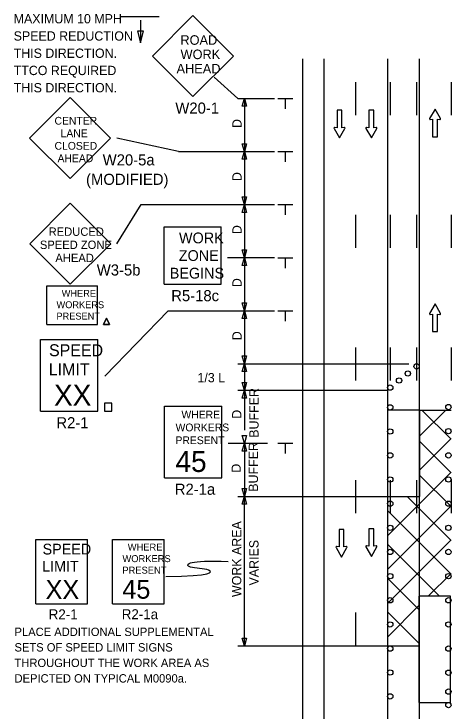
# Model space of a CAD drawing. Extents: x 16730 to 18475, y 5651 to 6927.
# Drawn here: x 16730 to 17059, y 6401 to 6927 of the extents above; entities that cross this region are included whole.
import ezdxf

# ---------------------------------------------------------------- set-up
doc = ezdxf.new("R2010")
doc.units = 0
for name, color, linetype in [('ALI_LEGAL_EX', 7, 'Continuous'), ('Level 6', 7, 'Continuous'), ('MT_SCRATCH_LEVEL_A', 7, 'Continuous'), ('MT_SCRATCH_LEVEL_E', 7, 'Continuous'), ('PAVT_EDGE_EX', 7, 'Continuous'), ('TRAFFIC_SIGNS_PR', 7, 'Continuous'), ('TYPICAL_TEXT_DIMEN_PR', 7, 'Continuous')]:
    doc.layers.add(name, color=color, linetype=linetype)

msp = doc.modelspace()

# ---------------------------------------------------------------- linework, layer by layer
at = {"layer": 'ALI_LEGAL_EX'}
for points in [[(16987.43, 6875.6), (16987.43, 6850.6)], [(17013.43, 6875.6), (17013.43, 6850.6)], [(17033.43, 6875.6), (17033.43, 6850.6)], [(17059.43, 6875.6), (17059.43, 6850.6)], [(16987.43, 6775.6), (16987.43, 6750.6)], [(17013.43, 6775.6), (17013.43, 6750.6)], [(17033.43, 6775.6), (17033.43, 6750.6)], [(17059.43, 6775.6), (17059.43, 6750.6)], [(16987.43, 6675.6), (16987.43, 6650.6)], [(17013.43, 6675.6), (17013.43, 6650.6)], [(17033.43, 6675.6), (17033.43, 6650.6)], [(17059.43, 6675.6), (17059.43, 6650.6)], [(16987.43, 6575.6), (16987.43, 6550.6)], [(17013.43, 6575.6), (17013.43, 6550.6)], [(17033.43, 6575.6), (17033.43, 6550.6)], [(17059.43, 6575.6), (17059.43, 6550.6)], [(16987.43, 6475.6), (16987.43, 6450.6)]]:
    msp.add_lwpolyline(points, dxfattribs=at)
at = {"layer": 'Level 6'}
for p, q in [((16843.25, 6631.37), (16886.45, 6631.37)), ((16843.25, 6577.37), (16843.25, 6631.37)), ((16886.45, 6577.37), (16886.45, 6631.37)), ((16843.25, 6577.37), (16886.45, 6577.37))]:
    msp.add_line(p, q, dxfattribs=at)
at = {"layer": 'MT_SCRATCH_LEVEL_A'}
for p, q in [((17011.43, 6628.39), (17011.43, 6450.54)), ((17035.43, 6628.39), (17059.43, 6628.39)), ((17035.84, 6608.83), (17055.4, 6628.39)), ((17059.43, 6606.43), (17037.48, 6628.39)), ((17035.84, 6583.37), (17059.43, 6606.97)), ((17059.43, 6580.97), (17035.84, 6604.57)), ((17011.43, 6596.33), (17011.43, 6482.6)), ((17011.43, 6533.52), (17059.43, 6581.52)), ((17059.43, 6555.52), (17035.84, 6579.12)), ((17059.43, 6530.06), (17026.21, 6563.29)), ((17011.43, 6508.06), (17059.43, 6556.06)), ((17059.43, 6504.61), (17011.43, 6552.61)), ((17011.43, 6482.6), (17059.43, 6530.6)), ((17050.66, 6487.93), (17011.43, 6527.15)), ((17042.22, 6487.93), (17059.43, 6505.15)), ((17035.43, 6477.69), (17011.43, 6501.69)), ((17011.43, 6482.6), (17011.43, 6450.54)), ((17011.43, 6457.15), (17035.43, 6481.15)), ((17035.43, 6452.24), (17011.43, 6476.24)), ((17011.43, 6450.54), (17035.03, 6450.54))]:
    msp.add_line(p, q, dxfattribs=at)
at = {"layer": 'MT_SCRATCH_LEVEL_E'}
for p, q in [((16977.1, 6854.39), (16973.36, 6854.39)), ((16973.36, 6854.39), (16973.36, 6841.13)), ((16977.1, 6854.39), (16973.36, 6854.39)), ((16973.36, 6854.39), (16973.36, 6841.13)), ((16977.1, 6841.13), (16977.1, 6854.39)), ((16977.1, 6841.13), (16977.1, 6854.39)), ((17001.17, 6854.39), (16997.43, 6854.39)), ((16997.43, 6854.39), (16997.43, 6841.13)), ((17001.17, 6854.39), (16997.43, 6854.39)), ((16997.43, 6854.39), (16997.43, 6841.13)), ((17001.17, 6841.13), (17001.17, 6854.39)), ((17001.17, 6841.13), (17001.17, 6854.39)), ((17047.37, 6855.34), (17043.26, 6848.1)), ((17047.37, 6855.34), (17043.26, 6848.1)), ((17051.52, 6848.1), (17047.37, 6855.34)), ((17051.52, 6848.1), (17047.37, 6855.34)), ((17043.74, 6847.41), (17045.52, 6847.73)), ((17043.74, 6847.41), (17045.52, 6847.73)), ((17045.52, 6847.73), (17045.52, 6834.47)), ((17045.52, 6847.73), (17045.52, 6834.47)), ((17049.26, 6834.47), (17049.26, 6847.73)), ((17049.26, 6847.73), (17051.04, 6847.41)), ((17049.26, 6834.47), (17049.26, 6847.73)), ((17049.26, 6847.73), (17051.04, 6847.41)), ((16971.1, 6840.77), (16975.25, 6833.53)), ((16971.1, 6840.77), (16975.25, 6833.53)), ((16973.36, 6841.13), (16971.58, 6841.45)), ((16973.36, 6841.13), (16971.58, 6841.45)), ((16975.25, 6833.53), (16979.36, 6840.77)), ((16975.25, 6833.53), (16979.36, 6840.77)), ((16978.88, 6841.45), (16977.1, 6841.13)), ((16978.88, 6841.45), (16977.1, 6841.13)), ((16995.18, 6840.77), (16999.32, 6833.53)), ((16995.18, 6840.77), (16999.32, 6833.53)), ((16997.43, 6841.13), (16995.65, 6841.45)), ((16997.43, 6841.13), (16995.65, 6841.45)), ((16999.32, 6833.53), (17003.43, 6840.77)), ((16999.32, 6833.53), (17003.43, 6840.77)), ((17002.95, 6841.45), (17001.17, 6841.13)), ((17002.95, 6841.45), (17001.17, 6841.13)), ((17045.52, 6834.47), (17049.26, 6834.47)), ((17045.52, 6834.47), (17049.26, 6834.47)), ((17047.37, 6708.37), (17043.26, 6701.13)), ((17047.37, 6708.37), (17043.26, 6701.13)), ((17051.52, 6701.13), (17047.37, 6708.37)), ((17051.52, 6701.13), (17047.37, 6708.37)), ((17043.74, 6700.45), (17045.52, 6700.76)), ((17043.74, 6700.45), (17045.52, 6700.76)), ((17045.52, 6700.76), (17045.52, 6687.51)), ((17045.52, 6700.76), (17045.52, 6687.51)), ((17049.26, 6687.51), (17049.26, 6700.76)), ((17049.26, 6700.76), (17051.04, 6700.45)), ((17049.26, 6687.51), (17049.26, 6700.76)), ((17049.26, 6700.76), (17051.04, 6700.45)), ((17045.52, 6687.51), (17049.26, 6687.51)), ((17045.52, 6687.51), (17049.26, 6687.51)), ((17001.17, 6538.92), (16997.43, 6538.92)), ((16997.43, 6538.92), (16997.43, 6525.66)), ((17001.17, 6538.92), (16997.43, 6538.92)), ((16997.43, 6538.92), (16997.43, 6525.66)), ((17001.17, 6525.66), (17001.17, 6538.92)), ((17001.17, 6525.66), (17001.17, 6538.92)), ((16978.61, 6538.42), (16974.87, 6538.42)), ((16974.87, 6538.42), (16974.87, 6525.16)), ((16978.61, 6538.42), (16974.87, 6538.42)), ((16974.87, 6538.42), (16974.87, 6525.16)), ((16978.61, 6525.16), (16978.61, 6538.42)), ((16978.61, 6525.16), (16978.61, 6538.42)), ((16972.61, 6524.79), (16976.76, 6517.55)), ((16972.61, 6524.79), (16976.76, 6517.55)), ((16974.87, 6525.16), (16973.09, 6525.48)), ((16974.87, 6525.16), (16973.09, 6525.48)), ((16976.76, 6517.55), (16980.87, 6524.79)), ((16976.76, 6517.55), (16980.87, 6524.79)), ((16980.38, 6525.48), (16978.61, 6525.16)), ((16980.38, 6525.48), (16978.61, 6525.16)), ((16995.18, 6525.3), (16999.32, 6518.06)), ((16995.18, 6525.3), (16999.32, 6518.06)), ((16997.43, 6525.66), (16995.65, 6525.98)), ((16997.43, 6525.66), (16995.65, 6525.98)), ((16999.32, 6518.06), (17003.43, 6525.3)), ((16999.32, 6518.06), (17003.43, 6525.3)), ((17002.95, 6525.98), (17001.17, 6525.66)), ((17002.95, 6525.98), (17001.17, 6525.66))]:
    msp.add_line(p, q, dxfattribs=at)
for centre, start, end in [((17043.67, 6847.87), 150.4248, 279.9638), ((17043.67, 6847.87), 150.4248, 279.9638), ((17051.11, 6847.87), 260.0362, 29.7731), ((17051.11, 6847.87), 260.0362, 29.7731), ((16971.51, 6840.99), 80.0362, 209.7731), ((16971.51, 6840.99), 80.0362, 209.7731), ((16978.96, 6840.99), 330.4248, 99.9638), ((16978.96, 6840.99), 330.4248, 99.9638), ((16995.59, 6840.99), 80.0362, 209.7731), ((16995.59, 6840.99), 80.0362, 209.7731), ((17003.03, 6840.99), 330.4248, 99.9638), ((17003.03, 6840.99), 330.4248, 99.9638), ((17043.67, 6700.91), 150.4248, 279.9638), ((17043.67, 6700.91), 150.4248, 279.9638), ((17051.11, 6700.91), 260.0362, 29.7731), ((17051.11, 6700.91), 260.0362, 29.7731), ((16973.02, 6525.02), 80.0362, 209.7731), ((16973.02, 6525.02), 80.0362, 209.7731), ((16980.46, 6525.02), 330.4248, 99.9638), ((16980.46, 6525.02), 330.4248, 99.9638), ((16995.59, 6525.52), 80.0362, 209.7731), ((16995.59, 6525.52), 80.0362, 209.7731), ((17003.03, 6525.52), 330.4248, 99.9638), ((17003.03, 6525.52), 330.4248, 99.9638)]:
    msp.add_arc(centre, 0.463, start, end, dxfattribs=at)
at = {"layer": 'PAVT_EDGE_EX'}
for p, q in [((16947.43, 6893.09), (16947.43, 6095.81)), ((16963.43, 6893.09), (16963.43, 6095.81)), ((17011.43, 6893.09), (17011.43, 6095.81)), ((17035.43, 6893.09), (17035.43, 6095.81))]:
    msp.add_line(p, q, dxfattribs=at)
for points in [[(17035.84, 6628.39), (17011.43, 6628.39), (17011.43, 6563.29), (17035.84, 6563.29)], [(17058.97, 6487.93), (17035.03, 6487.93), (17035.03, 6407.93), (17058.97, 6407.93)]]:
    msp.add_lwpolyline(points, close=True, dxfattribs=at)
at = {"layer": 'TRAFFIC_SIGNS_PR'}
for p, q in [((16864.68, 6925.84), (16834.13, 6895.29)), ((16895.23, 6895.29), (16864.68, 6925.84)), ((16834.13, 6895.29), (16864.68, 6864.74)), ((16864.68, 6864.74), (16895.23, 6895.29)), ((16771.94, 6863.99), (16741.39, 6833.44)), ((16802.49, 6833.44), (16771.94, 6863.99)), ((16741.39, 6833.44), (16771.94, 6802.89)), ((16771.94, 6802.89), (16802.49, 6833.44)), ((16772.07, 6784.31), (16741.53, 6753.76)), ((16802.62, 6753.76), (16772.07, 6784.31)), ((16842.86, 6723.3), (16842.86, 6766.5)), ((16842.86, 6766.5), (16886.06, 6766.5)), ((16886.06, 6723.3), (16886.06, 6766.5)), ((16741.53, 6753.76), (16772.07, 6723.21)), ((16772.07, 6723.21), (16802.62, 6753.76)), ((16842.86, 6723.3), (16886.06, 6723.3)), ((16754.32, 6722.09), (16792.72, 6722.09)), ((16754.32, 6692.77), (16754.32, 6722.09)), ((16792.72, 6692.77), (16792.72, 6722.09)), ((16754.32, 6692.77), (16792.72, 6692.77)), ((16749.58, 6681.5), (16792.78, 6681.5)), ((16749.58, 6627.5), (16749.58, 6681.5)), ((16792.78, 6627.5), (16792.78, 6681.5)), ((16749.58, 6627.5), (16792.78, 6627.5)), ((16746.08, 6530.74), (16784.96, 6530.74)), ((16746.08, 6482.14), (16746.08, 6530.74)), ((16784.96, 6482.14), (16784.96, 6530.74)), ((16803.99, 6530.83), (16842.87, 6530.83)), ((16803.99, 6482.23), (16803.99, 6530.83)), ((16842.87, 6482.23), (16842.87, 6530.83)), ((16746.08, 6482.14), (16784.96, 6482.14)), ((16803.99, 6482.23), (16842.87, 6482.23))]:
    msp.add_line(p, q, dxfattribs=at)
for points in [[(16799.47, 6697.71), (16797.23, 6692.77)], [(16797.23, 6692.77), (16799.47, 6697.71)], [(16801.7, 6692.77), (16799.47, 6697.71)], [(16799.47, 6697.71), (16801.7, 6692.77)], [(16797.23, 6692.77), (16801.7, 6692.77)], [(16801.7, 6692.77), (16797.23, 6692.77)]]:
    msp.add_lwpolyline(points, dxfattribs=at)
msp.add_lwpolyline([(16797.79, 6627.5), (16803.39, 6627.5), (16803.39, 6633.68), (16797.79, 6633.68)], close=True, dxfattribs=at)
for centre in [(17033.43, 6661.25), (17026.8, 6655.93), (17020.17, 6650.62), (17013.53, 6645.3), (17013.53, 6630.4), (17057.41, 6630.63), (17013.53, 6612.21), (17057.41, 6612.42), (17013.53, 6594.21), (17057.41, 6594.21), (17013.53, 6575.99), (17057.41, 6575.99), (17013.53, 6557.78), (17057.41, 6557.78), (17013.53, 6539.56), (17057.41, 6539.56), (17013.53, 6521.35), (17057.41, 6521.35), (17013.53, 6503.13), (17057.41, 6503.13), (17013.53, 6484.92), (17057.41, 6484.92), (17013.53, 6466.71), (17057.41, 6466.71), (17013.53, 6448.49), (17057.41, 6448.49), (17013.53, 6430.49), (17057.41, 6430.28), (17057.4, 6416.06), (17013.53, 6412.49), (17057.41, 6405.88)]:
    msp.add_circle(centre, 2, dxfattribs=at)
at = {"layer": 'TYPICAL_TEXT_DIMEN_PR'}
for p, q in [((16839.27, 6924.79), (16809.83, 6924.79)), ((16825.09, 6922.29), (16825.09, 6905.16)), ((16825.09, 6913.96), (16822.74, 6913.96)), ((16822.74, 6913.96), (16825.09, 6905.16)), ((16825.09, 6905.16), (16827.45, 6913.96)), ((16827.45, 6913.96), (16825.09, 6913.96)), ((16898.43, 6863.28), (16880.75, 6879.36)), ((16898.43, 6863.28), (16926.23, 6863.28)), ((16901.86, 6857.42), (16903.43, 6863.28)), ((16903.43, 6863.28), (16903.43, 6823.28)), ((16903.43, 6863.28), (16905, 6857.42)), ((16928.68, 6863.25), (16939.93, 6863.25)), ((16934.31, 6863.25), (16934.31, 6855.46)), ((16903.43, 6857.42), (16901.86, 6857.42)), ((16905, 6857.42), (16903.43, 6857.42)), ((16853.87, 6823.28), (16807.31, 6833.45)), ((16903.43, 6823.28), (16901.86, 6829.14)), ((16901.86, 6829.14), (16903.43, 6829.14)), ((16903.43, 6829.14), (16905, 6829.14)), ((16905, 6829.14), (16903.43, 6823.28)), ((16853.87, 6823.28), (16926.23, 6823.28)), ((16901.86, 6817.42), (16903.43, 6823.28)), ((16903.43, 6823.28), (16903.43, 6783.28)), ((16903.43, 6823.28), (16905, 6817.42)), ((16928.68, 6823.25), (16939.93, 6823.25)), ((16934.31, 6823.25), (16934.31, 6815.46)), ((16903.43, 6817.42), (16901.86, 6817.42)), ((16905, 6817.42), (16903.43, 6817.42)), ((16903.43, 6783.28), (16901.86, 6789.14)), ((16901.86, 6789.14), (16903.43, 6789.14)), ((16903.43, 6789.14), (16905, 6789.14)), ((16905, 6789.14), (16903.43, 6783.28)), ((16807.31, 6753.71), (16825.55, 6783.28)), ((16825.55, 6783.28), (16926.23, 6783.28)), ((16901.86, 6777.42), (16903.43, 6783.28)), ((16903.43, 6783.28), (16903.43, 6743.28)), ((16903.43, 6783.28), (16905, 6777.42)), ((16928.68, 6783.25), (16939.93, 6783.25)), ((16934.31, 6783.25), (16934.31, 6775.46)), ((16903.43, 6777.42), (16901.86, 6777.42)), ((16905, 6777.42), (16903.43, 6777.42)), ((16903.43, 6743.28), (16901.86, 6749.14)), ((16901.86, 6749.14), (16903.43, 6749.14)), ((16903.43, 6749.14), (16905, 6749.14)), ((16905, 6749.14), (16903.43, 6743.28)), ((16890.71, 6743.28), (16926.23, 6743.28)), ((16901.86, 6737.42), (16903.43, 6743.28)), ((16903.43, 6743.28), (16903.43, 6703.28)), ((16903.43, 6743.28), (16905, 6737.42)), ((16928.68, 6743.25), (16939.93, 6743.25)), ((16934.31, 6743.25), (16934.31, 6735.46)), ((16903.43, 6737.42), (16901.86, 6737.42)), ((16905, 6737.42), (16903.43, 6737.42)), ((16903.43, 6703.28), (16901.86, 6709.14)), ((16901.86, 6709.14), (16903.43, 6709.14)), ((16903.43, 6709.14), (16905, 6709.14)), ((16905, 6709.14), (16903.43, 6703.28)), ((16798.11, 6654.04), (16845.86, 6703.28)), ((16845.86, 6703.28), (16926.23, 6703.28)), ((16901.86, 6697.42), (16903.43, 6703.28)), ((16903.43, 6703.28), (16903.43, 6663.28)), ((16903.43, 6703.28), (16905, 6697.42)), ((16928.68, 6703.25), (16939.93, 6703.25)), ((16934.31, 6703.25), (16934.31, 6695.46)), ((16903.43, 6697.42), (16901.86, 6697.42)), ((16905, 6697.42), (16903.43, 6697.42)), ((16903.43, 6663.28), (16901.86, 6669.14)), ((16901.86, 6669.14), (16903.43, 6669.14)), ((16903.43, 6669.14), (16905, 6669.14)), ((16905, 6669.14), (16903.43, 6663.28)), ((16898.43, 6663.28), (17027.57, 6663.28)), ((16901.86, 6657.42), (16903.43, 6663.28)), ((16903.43, 6663.28), (16903.43, 6643.29)), ((16903.43, 6663.28), (16905, 6657.42)), ((16903.43, 6657.42), (16901.86, 6657.42)), ((16905, 6657.42), (16903.43, 6657.42)), ((16903.43, 6643.29), (16901.86, 6649.15)), ((16901.86, 6649.15), (16903.43, 6649.15)), ((16903.43, 6649.15), (16905, 6649.15)), ((16905, 6649.15), (16903.43, 6643.29)), ((16898.43, 6643.29), (17011.43, 6643.29)), ((16901.86, 6637.43), (16903.43, 6643.29)), ((16903.43, 6643.29), (16903.43, 6613.29)), ((16903.43, 6643.29), (16905, 6637.43)), ((16903.43, 6637.43), (16901.86, 6637.43)), ((16905, 6637.43), (16903.43, 6637.43)), ((16903.43, 6603.29), (16901.86, 6609.15)), ((16901.86, 6609.15), (16903.43, 6609.15)), ((16903.43, 6609.15), (16905, 6609.15)), ((16905, 6609.15), (16903.43, 6603.29)), ((16891.23, 6603.29), (16920.81, 6603.29)), ((16901.86, 6597.43), (16903.43, 6603.29)), ((16903.43, 6603.29), (16903.43, 6563.29)), ((16903.43, 6603.29), (16905, 6597.43)), ((16928.68, 6603.29), (16939.93, 6603.29)), ((16934.31, 6603.29), (16934.31, 6595.5)), ((16903.43, 6597.43), (16901.86, 6597.43)), ((16905, 6597.43), (16903.43, 6597.43)), ((16903.43, 6563.29), (16901.86, 6569.15)), ((16901.86, 6569.15), (16903.43, 6569.15)), ((16903.43, 6569.15), (16905, 6569.15)), ((16905, 6569.15), (16903.43, 6563.29)), ((16898.43, 6563.29), (17011.43, 6563.29)), ((16901.86, 6557.43), (16903.43, 6563.29)), ((16903.43, 6450.54), (16903.43, 6563.29)), ((16903.43, 6563.29), (16905, 6557.43)), ((16903.43, 6557.43), (16901.86, 6557.43)), ((16905, 6557.43), (16903.43, 6557.43)), ((16903.43, 6450.54), (16901.86, 6456.41)), ((16901.86, 6456.41), (16903.43, 6456.41)), ((16903.43, 6456.41), (16905, 6456.41)), ((16905, 6456.41), (16903.43, 6450.54)), ((16898.43, 6450.54), (17011.43, 6450.54))]:
    msp.add_line(p, q, dxfattribs=at)
msp.add_open_spline([(16844.3, 6502.9), (16879.91, 6503.22), (16879.91, 6509.06), (16859.26, 6509.06), (16860.59, 6514.24), (16875.86, 6514.61), (16891.26, 6514.27)], degree=3, dxfattribs=at)

# ---------------------------------------------------------------- texts
at = {"layer": 'Level 6'}
for s, height, p in [('45', 15.785, (16851.47, 6581.7)), ('R2-1a', 8.37, (16850.96, 6564.5))]:
    msp.add_text(s, height=height, dxfattribs=at).set_placement(p)
at = {"layer": 'TRAFFIC_SIGNS_PR'}
for s, height, p in [('ROAD', 7.2, (16855.17, 6903.77)), ('WORK', 7.2, (16855.29, 6892.97)), ('AHEAD', 7.2, (16852.26, 6882.17)), ('W20-1', 8.37, (16851.37, 6851.87)), ('CENTER', 5.85, (16760.21, 6843.57)), ('LANE', 5.85, (16764.8, 6834.12)), ('CLOSED', 5.85, (16760.22, 6824.67)), ('AHEAD', 5.85, (16762.5, 6815.22)), ('W20-5a', 8.37, (16796.54, 6812.82)), ('(MODIFIED)', 8.37, (16784, 6798.15)), ('REDUCED', 6.3, (16755.79, 6759.73)), ('WORK', 8.119, (16854.11, 6754.09)), ('SPEED ZONE', 6.3, (16749.17, 6749.83)), ('AHEAD', 6.3, (16760.84, 6739.93)), ('ZONE', 8.119, (16853.97, 6740.8)), ('W3-5b', 8.37, (16792.08, 6729.79)), ('BEGINS', 8.119, (16847.14, 6727.52)), ('WHERE', 5.2, (16765.63, 6713.77)), ('R5-18c', 8.37, (16848.27, 6710.43)), ('WORKERS', 5.2, (16761.7, 6705.17)), ('PRESENT', 5.2, (16761.63, 6696.57)), ('SPEED', 9, (16756.06, 6668.97)), ('LIMIT', 9, (16755.88, 6654.57)), ('XX', 15.785, (16759.83, 6631.73)), ('R2-1', 8.37, (16761.59, 6614.63)), ('WHERE', 5.85, (16855.97, 6622.01)), ('WORKERS', 5.85, (16851.55, 6612.34)), ('PRESENT', 5.85, (16851.48, 6602.66)), ('SPEED', 8.1, (16751.17, 6519.46)), ('WHERE', 5.265, (16815.44, 6522.41)), ('WORKERS', 5.265, (16811.46, 6513.7)), ('LIMIT', 8.1, (16750.84, 6506.5)), ('PRESENT', 5.265, (16811.39, 6504.99)), ('XX', 14.206, (16753.47, 6485.95)), ('45', 14.206, (16811.38, 6486.13)), ('R2-1', 7.533, (16755.81, 6470.56)), ('R2-1a', 7.533, (16810.93, 6470.65)), ('PLACE ADDITIONAL SUPPLEMENTAL', 6.3, (16730.01, 6458)), ('SETS OF SPEED LIMIT SIGNS', 6.3, (16730.01, 6446.3)), ('THROUGHOUT THE WORK AREA AS', 6.3, (16730.01, 6434.6)), ('DEPICTED ON TYPICAL M0090a.', 6.3, (16730.01, 6422.9))]:
    msp.add_text(s, height=height, dxfattribs=at).set_placement(p)
at = {"layer": 'TYPICAL_TEXT_DIMEN_PR'}
for s, p in [('MAXIMUM 10 MPH', (16729.36, 6919.93)), ('SPEED REDUCTION', (16729.36, 6906.93)), ('THIS DIRECTION.', (16729.36, 6893.93)), ('TTCO REQUIRED', (16729.36, 6880.93)), ('THIS DIRECTION.', (16729.36, 6867.93)), ('1/3 L', (16868.07, 6649.29))]:
    msp.add_text(s, height=7, dxfattribs=at).set_placement(p)
for s, p in [('D', (16901.37, 6841.03)), ('D', (16901.37, 6801.03)), ('D', (16901.37, 6761.03)), ('D', (16901.37, 6721.03)), ('D', (16901.37, 6681.03)), ('BUFFER', (16914.19, 6607.48)), ('D', (16901.19, 6621.84)), ('BUFFER', (16913.75, 6566.77)), ('D', (16900.75, 6581.13)), ('WORK AREA', (16901.13, 6487.37)), ('VARIES', (16914.13, 6496.09))]:
    msp.add_text(s, height=7, rotation=90, dxfattribs=at).set_placement(p)

doc.saveas('drawing.dxf')
